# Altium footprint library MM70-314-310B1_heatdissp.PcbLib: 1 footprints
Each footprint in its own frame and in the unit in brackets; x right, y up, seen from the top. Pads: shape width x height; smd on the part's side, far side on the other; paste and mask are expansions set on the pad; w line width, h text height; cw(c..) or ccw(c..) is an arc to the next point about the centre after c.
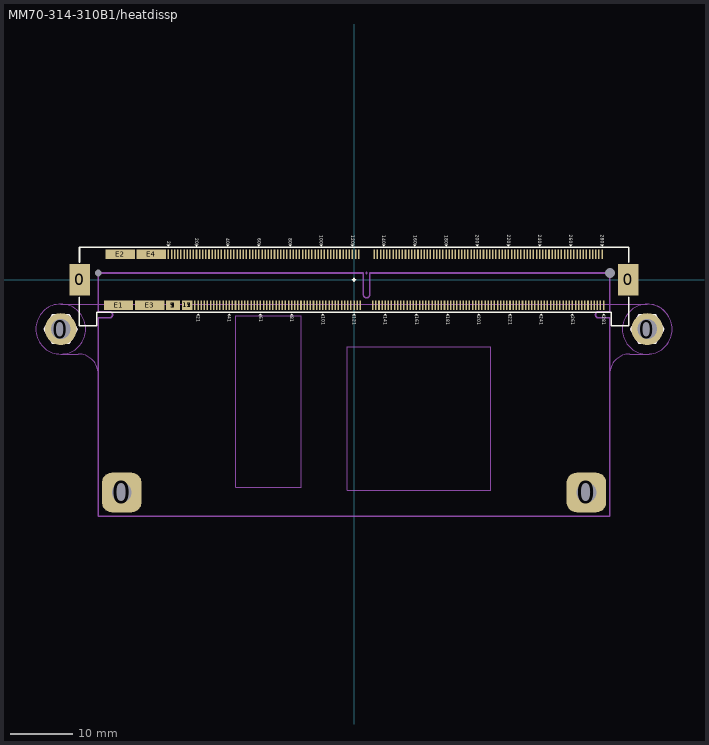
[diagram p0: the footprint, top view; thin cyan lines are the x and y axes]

## MM70-314-310B1/heatdissp [mm]
pads (286):
  round 5.1 hole 3.175: 0(-47.011,-7.897) 0(47.011,-7.897)
  rect 3.3x5 smd: 0(-43.95,0) 0(43.95,0)
  rrect50% 6.35x6.35 hole 3.175: 0(-37.236,-34.087) 0(37.236,-34.087)
  round 0 hole 1.1 unplated: 0A(-41,1.1)
  round 0 hole 1.6 unplated: 0B(41,1.1)
  rect 2.23x1.5 smd paste-0.225 mask+0.076: 1(-29,-4.1) 3(-29,-4.1) 5(-29,-4.1) 7(-29,-4.1) 9(-29,-4.1)
  rect 0.245x1.5 smd paste+0 mask+0.076: 2(-29.75,4.1) 4(-29.25,4.1) 6(-28.75,4.1) 8(-28.25,4.1) 10(-27.75,4.1) 12(-27.25,4.1) 14(-26.75,4.1) 16(-26.25,4.1) 18(-25.75,4.1) 19(-25.5,-4.1) 20(-25.25,4.1) 21(-25,-4.1) 22(-24.75,4.1) 23(-24.5,-4.1) 24(-24.25,4.1) 25(-24,-4.1) 26(-23.75,4.1) 27(-23.5,-4.1) 28(-23.25,4.1) 29(-23,-4.1) 30(-22.75,4.1) 31(-22.5,-4.1) 32(-22.25,4.1) 33(-22,-4.1) 34(-21.75,4.1) 35(-21.5,-4.1) 36(-21.25,4.1) 37(-21,-4.1) 38(-20.75,4.1) 39(-20.5,-4.1) 40(-20.25,4.1) 41(-20,-4.1) 42(-19.75,4.1) 43(-19.5,-4.1) 44(-19.25,4.1) 45(-19,-4.1) 46(-18.75,4.1) 47(-18.5,-4.1) 48(-18.25,4.1) 49(-18,-4.1) 50(-17.75,4.1) 51(-17.5,-4.1) 52(-17.25,4.1) 53(-17,-4.1) 54(-16.75,4.1) 55(-16.5,-4.1) 56(-16.25,4.1) 57(-16,-4.1) 58(-15.75,4.1) 59(-15.5,-4.1) 60(-15.25,4.1) 61(-15,-4.1) 62(-14.75,4.1) 63(-14.5,-4.1) 64(-14.25,4.1) 65(-14,-4.1) 66(-13.75,4.1) 67(-13.5,-4.1) 68(-13.25,4.1) 69(-13,-4.1) 70(-12.75,4.1) 71(-12.5,-4.1) 72(-12.25,4.1) 73(-12,-4.1) 74(-11.75,4.1) 75(-11.5,-4.1) 76(-11.25,4.1) 77(-11,-4.1) 78(-10.75,4.1) 79(-10.5,-4.1) 80(-10.25,4.1) 81(-10,-4.1) 82(-9.75,4.1) 83(-9.5,-4.1) 84(-9.25,4.1) 85(-9,-4.1) 86(-8.75,4.1) 87(-8.5,-4.1) 88(-8.25,4.1) 89(-8,-4.1) 90(-7.75,4.1) 91(-7.5,-4.1) 92(-7.25,4.1) 93(-7,-4.1) 94(-6.75,4.1) 95(-6.5,-4.1) 96(-6.25,4.1) 97(-6,-4.1) 98(-5.75,4.1) 99(-5.5,-4.1) 100(-5.25,4.1) 101(-5,-4.1) 102(-4.75,4.1) 103(-4.5,-4.1) 104(-4.25,4.1) 105(-4,-4.1) 106(-3.75,4.1) 107(-3.5,-4.1) 108(-3.25,4.1) 109(-3,-4.1) 110(-2.75,4.1) 111(-2.5,-4.1) 112(-2.25,4.1) 113(-2,-4.1) 114(-1.75,4.1) 115(-1.5,-4.1) 116(-1.25,4.1) 117(-1,-4.1) 118(-0.75,4.1) 119(-0.5,-4.1) 120(-0.25,4.1) 121(0,-4.1) 122(0.25,4.1) 123(0.5,-4.1) 124(0.75,4.1) 125(1,-4.1) 133(3,-4.1) 134(3.25,4.1) 135(3.5,-4.1) 136(3.75,4.1) 137(4,-4.1) 138(4.25,4.1) 139(4.5,-4.1) 140(4.75,4.1) 141(5,-4.1) 142(5.25,4.1) 143(5.5,-4.1) 144(5.75,4.1) 145(6,-4.1) 146(6.25,4.1) 147(6.5,-4.1) 148(6.75,4.1) 149(7,-4.1) 150(7.25,4.1) 151(7.5,-4.1) 152(7.75,4.1) 153(8,-4.1) 154(8.25,4.1) 155(8.5,-4.1) 156(8.75,4.1) 157(9,-4.1) 158(9.25,4.1) 159(9.5,-4.1) 160(9.75,4.1) 161(10,-4.1) 162(10.25,4.1) 163(10.5,-4.1) 164(10.75,4.1) 165(11,-4.1) 166(11.25,4.1) 167(11.5,-4.1) 168(11.75,4.1) 169(12,-4.1) 170(12.25,4.1) 171(12.5,-4.1) 172(12.75,4.1) 173(13,-4.1) 174(13.25,4.1) 175(13.5,-4.1) 176(13.75,4.1) 177(14,-4.1) 178(14.25,4.1) 179(14.5,-4.1) 180(14.75,4.1) 181(15,-4.1) 182(15.25,4.1) 183(15.5,-4.1) 184(15.75,4.1) 185(16,-4.1) 186(16.25,4.1) 187(16.5,-4.1) 188(16.75,4.1) 189(17,-4.1) 190(17.25,4.1) 191(17.5,-4.1) 192(17.75,4.1) 193(18,-4.1) 194(18.25,4.1) 195(18.5,-4.1) 196(18.75,4.1) 197(19,-4.1) 198(19.25,4.1) 199(19.5,-4.1) 200(19.75,4.1) 201(20,-4.1) 202(20.25,4.1) 203(20.5,-4.1) 204(20.75,4.1) 205(21,-4.1) 206(21.25,4.1) 207(21.5,-4.1) 208(21.75,4.1) 209(22,-4.1) 210(22.25,4.1) 211(22.5,-4.1) 212(22.75,4.1) 213(23,-4.1) 214(23.25,4.1) 215(23.5,-4.1) 216(23.75,4.1) 217(24,-4.1) 218(24.25,4.1) 219(24.5,-4.1) 220(24.75,4.1) 221(25,-4.1) 222(25.25,4.1) 223(25.5,-4.1) 224(25.75,4.1) 225(26,-4.1) 226(26.25,4.1) 227(26.5,-4.1) 228(26.75,4.1) 229(27,-4.1) 230(27.25,4.1) 231(27.5,-4.1) 232(27.75,4.1) 233(28,-4.1) 234(28.25,4.1) 235(28.5,-4.1) 236(28.75,4.1) 237(29,-4.1) 238(29.25,4.1) 239(29.5,-4.1) 240(29.75,4.1) 241(30,-4.1) 242(30.25,4.1) 243(30.5,-4.1) 244(30.75,4.1) 245(31,-4.1) 246(31.25,4.1) 247(31.5,-4.1) 248(31.75,4.1) 249(32,-4.1) 250(32.25,4.1) 251(32.5,-4.1) 252(32.75,4.1) 253(33,-4.1) 254(33.25,4.1) 255(33.5,-4.1) 256(33.75,4.1) 257(34,-4.1) 258(34.25,4.1) 259(34.5,-4.1) 260(34.75,4.1) 261(35,-4.1) 262(35.25,4.1) 263(35.5,-4.1) 264(35.75,4.1) 265(36,-4.1) 266(36.25,4.1) 267(36.5,-4.1) 268(36.75,4.1) 269(37,-4.1) 270(37.25,4.1) 271(37.5,-4.1) 272(37.75,4.1) 273(38,-4.1) 274(38.25,4.1) 275(38.5,-4.1) 276(38.75,4.1) 277(39,-4.1) 278(39.25,4.1) 279(39.5,-4.1) 280(39.75,4.1) 281(40,-4.1)
  rect 1.73x1.5 smd paste-0.225 mask+0.076: 11(-26.75,-4.1) 13(-26.75,-4.1) 15(-26.75,-4.1) 17(-26.75,-4.1)
  rect 4.72x1.5 smd paste-0.225 mask+0.076: E1(-37.75,-4.1) E2(-37.5,4.1) E3(-32.75,-4.1) E4(-32.5,4.1)
Top Overlay:
  drawing of 53 lines, arcs and shapes, not listed
  text "281" at 39.788,-5.806 h0.51
  text "20" at -25.465,6.692 h0.51
  text "40" at -20.465,6.692 h0.51
  text "60" at -15.465,6.692 h0.51
  text "80" at -10.465,6.692 h0.51
  text "100" at -5.465,7.115 h0.51
  text "120" at -0.465,7.115 h0.51
  text "140" at 4.535,7.115 h0.51
  text "160" at 9.535,7.115 h0.51
  text "180" at 14.535,7.115 h0.51
  text "200" at 19.535,7.2 h0.51
  text "220" at 24.535,7.2 h0.51
  text "240" at 29.535,7.2 h0.51
  text "260" at 34.535,7.2 h0.51
  text "280" at 39.535,7.2 h0.51
  text "2" at -29.965,6.184 h0.51
  text "21" at -25.213,-5.806 h0.51
  text "41" at -20.213,-5.806 h0.51
  text "61" at -15.213,-5.806 h0.51
  text "81" at -10.213,-5.806 h0.51
  text "101" at -5.213,-5.806 h0.51
  text "121" at -0.213,-5.806 h0.51
  text "141" at 4.787,-5.806 h0.51
  text "161" at 9.787,-5.806 h0.51
  text "181" at 14.787,-5.806 h0.51
  text "201" at 19.787,-5.806 h0.51
  text "221" at 24.787,-5.806 h0.51
  text "241" at 29.787,-5.806 h0.51
  text "261" at 34.787,-5.806 h0.51
Bottom Overlay:
  lines w0.219: -49.644,-7.897 -48.325,-5.613 ; -49.644,-7.897 -48.325,-10.181 ; -49.644,-7.897 -48.325,-10.181 ; -49.644,-7.897 -48.325,-5.613 ; -48.325,-10.181 -45.688,-10.181 ; -48.325,-10.181 -45.688,-10.181 ; -48.325,-5.613 -45.688,-5.613 ; -48.325,-5.613 -45.688,-5.613 ; -45.688,-10.181 -44.369,-7.897 ; -45.688,-10.181 -44.369,-7.897 ; -45.688,-5.613 -44.369,-7.897 ; -45.688,-5.613 -44.369,-7.897 ; 44.356,-7.897 45.675,-5.613 ; 44.356,-7.897 45.675,-10.181 ; 44.356,-7.897 45.675,-10.181 ; 44.356,-7.897 45.675,-5.613 ; 45.675,-10.181 48.312,-10.181 ; 45.675,-10.181 48.312,-10.181 ; 45.675,-5.613 48.312,-5.613 ; 45.675,-5.613 48.312,-5.613 ; 48.312,-10.181 49.631,-7.897 ; 48.312,-10.181 49.631,-7.897 ; 48.312,-5.613 49.631,-7.897 ; 48.312,-5.613 49.631,-7.897
Mechanical 1:
  lines w0.051: 1.8,1.1 2.2,1.1 ; 2,0.9 2,1.3
  lines w0.254: -41,-37.897 41,-37.897 41,-6.1 39.2,-6.1 cw(c39.2,-5.6) 39.2,-5.1 41,-5.1 41,1.1 2.5,1.1 2.5,-2.4 cw(c2,-2.4) 1.5,-2.4 1.5,1.1 -41,1.1 -41,-5.1 -39.2,-5.1 cw(c-39.2,-5.6) -39.2,-6.1 -41,-6.1 -41,-37.897
Mechanical 13:
  circle w0.2: c46.994,-7.934 r4
  circle w0.2: c-47.006,-7.897 r4
  circle w0.152: c37.224,-34.087 r1.59
  circle w0.152: c-37.236,-34.087 r1.59
  circle w0.152: c-47.006,-7.897 r1.59
  circle w0.152: c46.994,-7.897 r1.59
  lines w0.152: -48.606,-7.897 -45.416,-7.897 ; -47.006,-9.484 -47.006,-6.284 ; -38.826,-34.087 -35.646,-34.087 ; -37.236,-35.654 -37.236,-32.484 ; 35.634,-34.087 38.814,-34.087 ; 37.224,-35.654 37.224,-34.087 37.224,-32.484 ; 45.394,-7.897 48.584,-7.897 ; 46.994,-9.484 46.994,-6.384 ; -47.006,-11.897 cw(c-47.006,-7.897) -47.006,-3.897 -41.006,-3.897 40.994,-3.897 46.994,-3.897 cw(c46.994,-7.897) 46.994,-11.897 44.169,-11.897 ccw(c44.169,-15.072) 40.994,-15.072 40.994,-37.897 -41.006,-37.897 -41.006,-15.072 ccw(c-44.181,-15.072) -44.181,-11.897 -47.006,-11.897 ; -18.977,-33.264 -18.977,-5.764 -8.477,-5.764 -8.477,-33.264 -18.977,-33.264 ; -1.077,-33.754 -1.077,-10.754 21.923,-10.754 21.923,-33.754 -1.077,-33.754
  lines w0.219: -49.644,-7.897 -48.325,-10.181 -45.688,-10.181 -44.369,-7.897 -45.688,-5.613 -48.325,-5.613 -49.644,-7.897 ; 44.356,-7.897 45.675,-10.181 48.312,-10.181 49.631,-7.897 48.312,-5.613 45.675,-5.613 44.356,-7.897
Mechanical 14:
  lines w0.219: -49.644,-7.897 -48.325,-5.613 -45.688,-5.613 -44.369,-7.897 -45.688,-10.181 -48.325,-10.181 -49.644,-7.897 ; 44.356,-7.897 45.675,-5.613 48.312,-5.613 49.631,-7.897 48.312,-10.181 45.675,-10.181 44.356,-7.897
Mechanical 15:
  circle w0.152: c46.994,-7.897 r1.59
  circle w0.152: c-47.006,-7.897 r1.59
  circle w0.152: c-37.236,-34.087 r1.59
  circle w0.152: c37.224,-34.087 r1.59
  circle w0.2: c-47.006,-7.897 r4
  circle w0.2: c46.994,-7.934 r4
  lines w0.152: -48.606,-7.897 -45.416,-7.897 ; -47.006,-9.484 -47.006,-6.284 ; -38.826,-34.087 -35.646,-34.087 ; -37.236,-35.654 -37.236,-32.484 ; 35.634,-34.087 38.814,-34.087 ; 37.224,-35.654 37.224,-34.087 37.224,-32.484 ; 45.394,-7.897 48.584,-7.897 ; 46.994,-9.484 46.994,-6.384 ; -47.006,-11.897 cw(c-47.006,-7.897) -47.006,-3.897 -41.006,-3.897 40.994,-3.897 46.994,-3.897 cw(c46.994,-7.897) 46.994,-11.897 44.169,-11.897 ccw(c44.169,-15.072) 40.994,-15.072 40.994,-37.897 -41.006,-37.897 -41.006,-15.072 ccw(c-44.181,-15.072) -44.181,-11.897 -47.006,-11.897 ; -18.977,-33.264 -8.477,-33.264 -8.477,-5.764 -18.977,-5.764 -18.977,-33.264 ; -1.077,-33.754 21.923,-33.754 21.923,-10.754 -1.077,-10.754 -1.077,-33.754
  lines w0.219: -49.638,-7.883 -48.32,-10.167 -45.682,-10.167 -44.364,-7.883 -45.682,-5.599 -48.32,-5.599 -49.638,-7.883 ; 44.362,-7.883 45.68,-10.167 48.318,-10.167 49.636,-7.883 48.318,-5.599 45.68,-5.599 44.362,-7.883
